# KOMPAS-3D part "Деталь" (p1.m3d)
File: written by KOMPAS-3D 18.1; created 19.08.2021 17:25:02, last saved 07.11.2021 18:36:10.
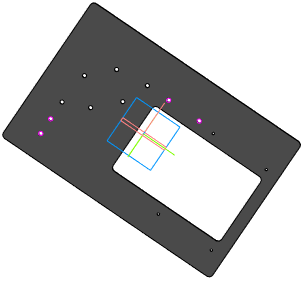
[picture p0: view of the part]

Document properties: Автор: 111; Полное имя файла: C:\Users\admin\Desktop\ffb\p1.m3d

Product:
- Part/product: Деталь
    Масса: 1.10029

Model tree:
1. Эскиз:1
2. Элемент выдавливания:1
     Расстояние 1 = 5
3. Эскиз:2  (with: Элемент выдавливания:1)
4. Элемент выдавливания:2
     Расстояние 2 = 5
5. Эскиз:3  (with: Элемент выдавливания:1)
6. Элемент выдавливания:3
     Расстояние 2 = 5
7. Эскиз:4  (with: Элемент выдавливания:1)
8. Элемент выдавливания:6
     Расстояние 2 = 5
9. Эскиз:5  (with: Элемент выдавливания:1)
10. Элемент выдавливания:7
     Расстояние 2 = 5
